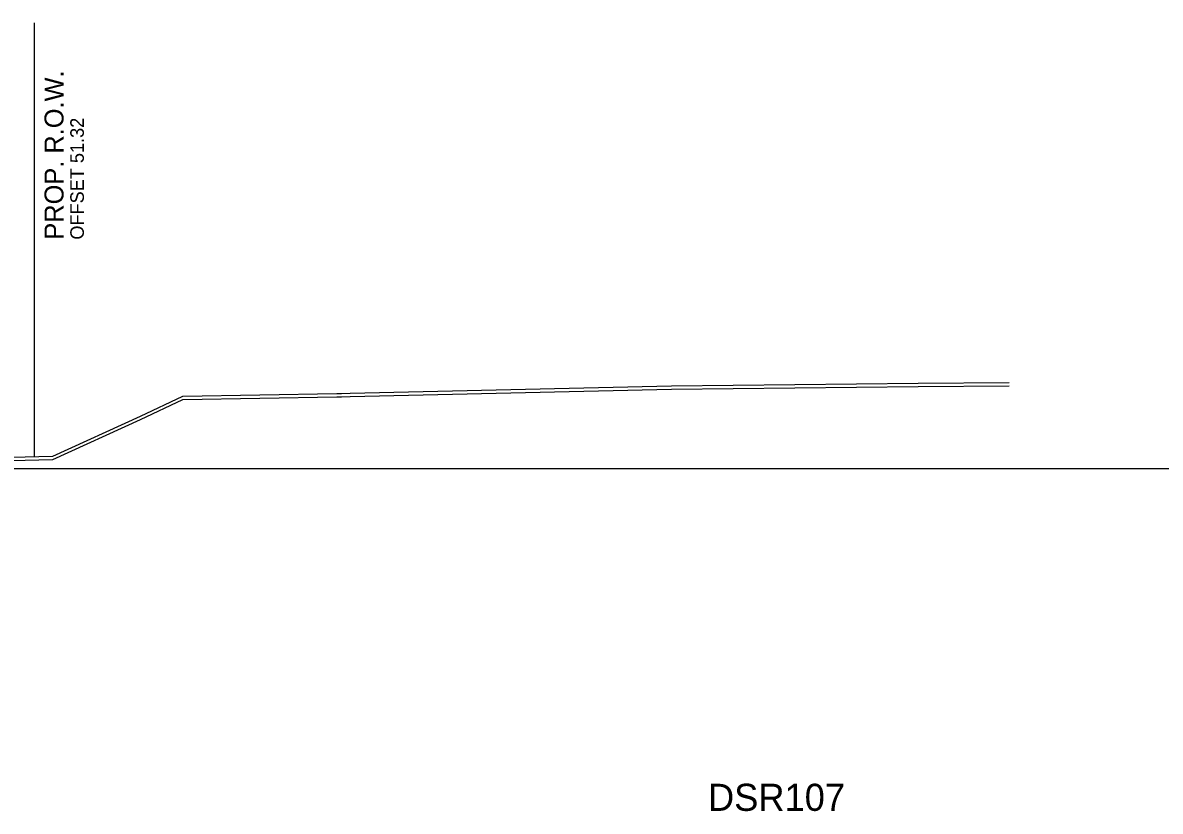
# Model space of a CAD drawing. Extents: x 1574 to 14903, y 7971 to 16537.
# Drawn here: x 4850.5 to 4934.4, y 9474.7 to 9532.9 of the extents above; entities that cross this region are included whole.
import ezdxf

# ---------------------------------------------------------------- set-up
doc = ezdxf.new("R2010")
doc.units = 0
for name, color, linetype in [('DESIGN - ROW - Right-of-Way and Easement Labels', 7, 'Continuous'), ('DESIGN - ROW - Right-of-Way Linework', 7, 'Continuous'), ('DESIGN - SHEET - Light Grid', 7, 'Continuous'), ('DESIGN - TYPICAL - Warning Text', 7, 'Continuous'), ('SURVEY - GROUND - Bottom of Topsoil Layer', 7, 'Continuous'), ('SURVEY - GROUND - Top of Ground', 7, 'Continuous')]:
    doc.layers.add(name, color=color, linetype=linetype)

msp = doc.modelspace()

# ---------------------------------------------------------------- linework, layer by layer
at = {"layer": 'DESIGN - ROW - Right-of-Way Linework'}
msp.add_line((4851.316, 9500.89), (4851.316, 9532.89), dxfattribs=at)
at = {"layer": 'DESIGN - SHEET - Light Grid'}
msp.add_line((4800, 9500), (5100, 9500), dxfattribs=at)
at = {"layer": 'SURVEY - GROUND - Bottom of Topsoil Layer'}
for p, q in [((4874.598, 9505.312), (4898.31, 9505.859)), ((4898.31, 9505.859), (4916.494, 9506.049)), ((4916.494, 9506.049), (4923.215, 9506.097)), ((4859.133, 9503.613), (4862.271, 9505.096)), ((4862.271, 9505.096), (4873.626, 9505.293)), ((4873.626, 9505.293), (4873.967, 9505.291)), ((4873.967, 9505.291), (4874.598, 9505.312)), ((4852.681, 9500.672), (4859.133, 9503.613)), ((4849.602, 9500.598), (4852.681, 9500.672))]:
    msp.add_line(p, q, dxfattribs=at)
at = {"layer": 'SURVEY - GROUND - Top of Ground'}
msp.add_lwpolyline([(4849.602, 9500.848), (4852.681, 9500.922), (4859.133, 9503.863), (4862.271, 9505.346), (4873.626, 9505.543), (4873.967, 9505.541), (4874.598, 9505.562), (4898.31, 9506.109), (4916.494, 9506.299), (4923.215, 9506.347)], dxfattribs=at)

# ---------------------------------------------------------------- texts
at = {"layer": 'DESIGN - ROW - Right-of-Way and Easement Labels'}
for s, height, p in [('PROP. R.O.W.', 1.4, (4853.466, 9516.89)), ('OFFSET 51.32', 1, (4854.966, 9516.89))]:
    msp.add_text(s, height=height, rotation=90, dxfattribs=at).set_placement(p)
at = {"layer": 'DESIGN - TYPICAL - Warning Text'}
msp.add_text('DSR107', height=2, dxfattribs=at).set_placement((4901, 9474.75))

doc.saveas('drawing.dxf')
